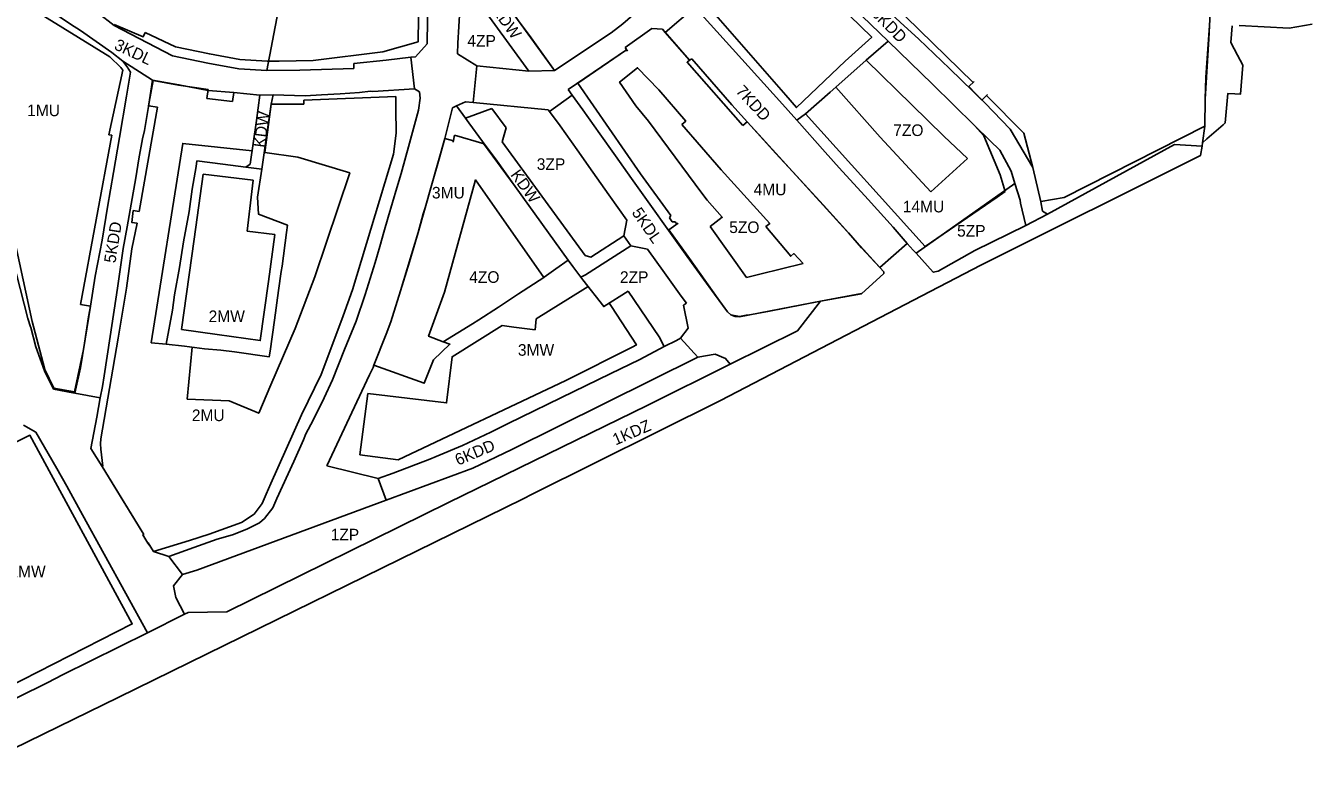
# Model space of a CAD drawing. Extents: x 7422310 to 7423642, y 5546060 to 5546927.
# Drawn here: x 7422901 to 7423455, y 5546113 to 5546434 of the extents above; entities that cross this region are included whole.
import ezdxf

# ---------------------------------------------------------------- set-up
doc = ezdxf.new("R2010")
doc.units = 0
for name, color, linetype in [('linie_rozgraniczajace', 7, 'Continuous'), ('linie_zabudowy_nieprzekraczalne', 7, 'Continuous'), ('linie_zabudowy_obowiązujace', 7, 'Continuous'), ('oznaczenia_przeznaczen', 7, 'Continuous')]:
    doc.layers.add(name, color=color, linetype=linetype)

msp = doc.modelspace()

# ---------------------------------------------------------------- linework, layer by layer
at = {"layer": 'linie_rozgraniczajace'}
for p, q in [((7423073.8, 5546425.75), (7423074.56, 5546477.74)), ((7423189.01, 5546441.58), (7423176.2, 5546430.66)), ((7423009.63, 5546439.75), (7423004.81, 5546414.23)), ((7423174.99, 5546432.06), (7423170.5, 5546432.37)), ((7423068.76, 5546420.18), (7423073.8, 5546425.75)), ((7423262.75, 5546418.7), (7423272.22, 5546426.88)), ((7422942.84, 5546418.27), (7422955.6, 5546410.13)), ((7423042.21, 5546417.2), (7423056.09, 5546418.71)), ((7423068.28, 5546406.4), (7423066.7, 5546419.94)), ((7423249.59, 5546407.03), (7423262.75, 5546418.7)), ((7423042.15, 5546415.05), (7423042.21, 5546417.2)), ((7423095.13, 5546416.2), (7423093.61, 5546400.5)), ((7423117.54, 5546413.93), (7423128.61, 5546414.21)), ((7423247.19, 5546404.93), (7423249.59, 5546407.03)), ((7423001.74, 5546403.6), (7423007.42, 5546403.74)), ((7423126.47, 5546396.57), (7423136.18, 5546403.62)), ((7423090.25, 5546393.7), (7423086.38, 5546399.01)), ((7423090.25, 5546393.7), (7423101.66, 5546397.94)), ((7423101.66, 5546397.94), (7423107.79, 5546389.55)), ((7423125.89, 5546397.37), (7423126.47, 5546396.57)), ((7423324.73, 5546388.94), (7423313.75, 5546400.32)), ((7423105.99, 5546383.55), (7423107.79, 5546389.55)), ((7423268.78, 5546385.58), (7423290.53, 5546362.07)), ((7423296.11, 5546386.01), (7423306.26, 5546376.43)), ((7422997.58, 5546373.98), (7422995.74, 5546372.63)), ((7423290.53, 5546362.07), (7423306.26, 5546376.43)), ((7423284.21, 5546335.6), (7423326.71, 5546365.57)), ((7423331.4, 5546347.59), (7423340.71, 5546352.47)), ((7423338.66, 5546353.63), (7423340.71, 5546352.47)), ((7423158.42, 5546343.08), (7423159.71, 5546349.88)), ((7423195.52, 5546347.13), (7423211.18, 5546325.11)), ((7423158.42, 5546343.08), (7423161.49, 5546338.78)), ((7423161.49, 5546338.78), (7423168.62, 5546337.4)), ((7423182.86, 5546298.95), (7423190.23, 5546290.85)), ((7422922.18, 5546275.32), (7422933.1, 5546273.27)), ((7422900.04, 5546261.52), (7422905.28, 5546258.55)), ((7422933.88, 5546243.7), (7422942.99, 5546228.95)), ((7423052.7, 5546238.61), (7423056.15, 5546229.3)), ((7422962.6, 5546205.08), (7422955.92, 5546207.18)), ((7422962.6, 5546205.08), (7422968.5, 5546197.26))]:
    msp.add_line(p, q, dxfattribs=at)
for points in [[(7423313.75, 5546400.32), (7423298.5, 5546415.11), (7423285.3, 5546427.74), (7423277.34, 5546435.03), (7423262.5, 5546448.96), (7423255.17, 5546455.86), (7423251.35, 5546459.53), (7423226, 5546483.92), (7423236.03, 5546494.6), (7423239.99, 5546499.12), (7423256.78, 5546518), (7423269.78, 5546532.29), (7423283.63, 5546547.12)], [(7423410.47, 5546433.48), (7423410.85, 5546441.62), (7423411.22, 5546452.41), (7423412.44, 5546471.67), (7423413.16, 5546487.99)], [(7423226, 5546483.92), (7423221.13, 5546476.36), (7423210.64, 5546464.93), (7423192.78, 5546445.64), (7423189.01, 5546441.58), (7423225.4, 5546401.19), (7423232.87, 5546392.89), (7423245.09, 5546379.05), (7423251.02, 5546372.38), (7423263.59, 5546358.66), (7423274.33, 5546346.76), (7423280.39, 5546339.82)], [(7423221.13, 5546476.36), (7423246.19, 5546452.06), (7423272.22, 5546426.88), (7423291.22, 5546408.42), (7423309.4, 5546390.63), (7423315.98, 5546384.15), (7423320.29, 5546380.02), (7423325.04, 5546370.95), (7423326.71, 5546365.57), (7423328.94, 5546358.36), (7423329.06, 5546357.09), (7423331.4, 5546347.59)], [(7423089.1, 5546469.47), (7423092.3, 5546464.88), (7423096.86, 5546458.12), (7423100.38, 5546453.19), (7423106.34, 5546444.85), (7423118.48, 5546428.31), (7423128.61, 5546414.21), (7423153, 5546430.51), (7423157.97, 5546434.29)], [(7422942.84, 5546418.27), (7422938.07, 5546422.01), (7422924.52, 5546431.41), (7422920.21, 5546434.18), (7422910.98, 5546440.54), (7422905.16, 5546444.71), (7422898.7, 5546448.79), (7422895.11, 5546450.46), (7422890.01, 5546452.75), (7422875.8, 5546457.17), (7422869.23, 5546459.14), (7422867.87, 5546459.46), (7422850.77, 5546464.93), (7422848.28, 5546453.48), (7422850.16, 5546448.92), (7422858.34, 5546432.53), (7422866.53, 5546416.28), (7422868.25, 5546412.95), (7422873.93, 5546400.01), (7422878.61, 5546392.2), (7422880.68, 5546389.97), (7422882.72, 5546383.91)], [(7422896.1, 5546464.02), (7422902.1, 5546461.88), (7422903.84, 5546461.21), (7422914.58, 5546452.89), (7422924.93, 5546444.52), (7422939, 5546433.61), (7422964.13, 5546420.6), (7422979.3, 5546417.43), (7422992.67, 5546414.98), (7423004.81, 5546414.23), (7423018.96, 5546414.36), (7423042.15, 5546415.05)], [(7423117.54, 5546413.93), (7423094.37, 5546445.85), (7423092.01, 5546447.67), (7423088.2, 5546447.7), (7423087.01, 5546425.95), (7423086.77, 5546421.45), (7423095.13, 5546416.2), (7423117.54, 5546413.93)], [(7423420.19, 5546433.55), (7423419.62, 5546426.25), (7423422.49, 5546420.89), (7423424.79, 5546416.61), (7423423.76, 5546404), (7423421.41, 5546404.17), (7423418.37, 5546404.38), (7423417.27, 5546391.68), (7423416.41, 5546390.93), (7423409.39, 5546384.8), (7423407.47, 5546383.13), (7423407.27, 5546381.7), (7423406.56, 5546377.62), (7423312.11, 5546330.42), (7423200.03, 5546272.25), (7423119.24, 5546231.93), (7423114.79, 5546229.75), (7422941.03, 5546144.48), (7422875.82, 5546112.55)], [(7423158.94, 5546424.1), (7423170.5, 5546432.37)], [(7423187.64, 5546419.3), (7423186.61, 5546418.64), (7423176.2, 5546430.66), (7423174.99, 5546432.06)], [(7423410.47, 5546433.48), (7423409.52, 5546419.62), (7423408.93, 5546411.19), (7423408.64, 5546401.87), (7423408.44, 5546390.23), (7423407.47, 5546383.13)], [(7423454.7, 5546434.19), (7423444.69, 5546432.48), (7423423.27, 5546433.58)], [(7423158.94, 5546424.1), (7423159.57, 5546423.17), (7423134.4, 5546406.07)], [(7422942.84, 5546418.27), (7422944.64, 5546415.83), (7422946.03, 5546413.53), (7422944.37, 5546403.26), (7422941.36, 5546385.4), (7422938.72, 5546370.37), (7422936.2, 5546355.47), (7422933.96, 5546341.18), (7422930.94, 5546325.71), (7422928.93, 5546312.84), (7422928.04, 5546308.14), (7422926.29, 5546296.91), (7422924.63, 5546286.28)], [(7423056.09, 5546418.71), (7423066.7, 5546419.94), (7423068.76, 5546420.18)], [(7423268.54, 5546329.5), (7423260.76, 5546337.96), (7423255.07, 5546344.32), (7423244.3, 5546356.22), (7423236.08, 5546365.29), (7423232.89, 5546368.81), (7423223.89, 5546378.5), (7423218.47, 5546384.35), (7423208.89, 5546395.05), (7423204.94, 5546399.47), (7423187.64, 5546419.3)], [(7423296.11, 5546386.01), (7423282.31, 5546399.53), (7423262.75, 5546418.7)], [(7423195.52, 5546347.13), (7423199.42, 5546350.06), (7423200.73, 5546351.04), (7423194.29, 5546358.45), (7423192.03, 5546361.38), (7423169.09, 5546392.38), (7423163.55, 5546399.02), (7423156.56, 5546409.23), (7423164.34, 5546415.42), (7423173.43, 5546405.92), (7423185.02, 5546392.5), (7423183.43, 5546390.95)], [(7422997.58, 5546373.98), (7423000.25, 5546392.66), (7423001.74, 5546403.6), (7422990.59, 5546404.8), (7422979.49, 5546405.69), (7422966.95, 5546408.1), (7422955.6, 5546410.13), (7422953.84, 5546398.71), (7422952.12, 5546388.38), (7422951.31, 5546384.86), (7422949.74, 5546376.23), (7422948.36, 5546368.1), (7422946.38, 5546356.7), (7422944.6, 5546346.93), (7422942.96, 5546337.61), (7422940.51, 5546320.54), (7422937.34, 5546299.69), (7422934.69, 5546282.86), (7422934.04, 5546278.27), (7422933.1, 5546273.27), (7422931.54, 5546264.99), (7422929.01, 5546251.47)], [(7423249.59, 5546407.03), (7423268.78, 5546385.58)], [(7423070.09, 5546397.23), (7423070.71, 5546402.27), (7423070.46, 5546405.03), (7423068.28, 5546406.4), (7423050.37, 5546405.21), (7423049.38, 5546405.29), (7423044.65, 5546404.83), (7423036.3, 5546404.24), (7423028.33, 5546403.75), (7423021.25, 5546403.36), (7423007.42, 5546403.74), (7423006.59, 5546399.81), (7423004.81, 5546386.78), (7423002.56, 5546371.78), (7423000.75, 5546359.7)], [(7423243.06, 5546314.91), (7423208.19, 5546308.26), (7423206.38, 5546308.39), (7423204.49, 5546309.09), (7423202.98, 5546310.29), (7423197.42, 5546317.97), (7423192.79, 5546324.22), (7423185.71, 5546334.11), (7423161.72, 5546367.72), (7423154.85, 5546377.47), (7423148.05, 5546387), (7423140.73, 5546397.36), (7423136.18, 5546403.62), (7423134.4, 5546406.07)], [(7423247.19, 5546404.93), (7423236.54, 5546395.6), (7423232.87, 5546392.89)], [(7422962.6, 5546205.08), (7422973.33, 5546208.83), (7422983.45, 5546212.48), (7422990.02, 5546214.37), (7422996.08, 5546216.82), (7423001.66, 5546219.51), (7423003.8, 5546221.4), (7423007.31, 5546225.96), (7423009.06, 5546229.93), (7423016.32, 5546245.9), (7423020.53, 5546255.26), (7423021.58, 5546257.84), (7423024.69, 5546263.69), (7423029.45, 5546273.3), (7423032.98, 5546281.12), (7423038.17, 5546294.1), (7423043.18, 5546306.38), (7423047.05, 5546317.8), (7423051.34, 5546331.52), (7423053.35, 5546338.41), (7423055.15, 5546344.58), (7423057.01, 5546351.04), (7423058.81, 5546357.44), (7423060.72, 5546363.72), (7423062.51, 5546369.9), (7423066.18, 5546382.92), (7423070.09, 5546397.23)], [(7423050.86, 5546287.45), (7423056.09, 5546300.76), (7423058.06, 5546306.11), (7423062.34, 5546319.38), (7423066.19, 5546331.82), (7423069.9, 5546344.45), (7423072.05, 5546352.59), (7423072.88, 5546355.17), (7423075.38, 5546363.7), (7423079.25, 5546377.16), (7423081.35, 5546385.04), (7423084.6, 5546398.19)], [(7423084.6, 5546398.19), (7423086.38, 5546399.01), (7423090.31, 5546400.82), (7423093.61, 5546400.5), (7423125.89, 5546397.37)], [(7423159.71, 5546349.88), (7423151.93, 5546360.78), (7423145.05, 5546370.53), (7423138.27, 5546380.06), (7423130.97, 5546390.37), (7423126.47, 5546396.57)], [(7423134.49, 5546332.65), (7423111.69, 5546364.32), (7423103.17, 5546376.16), (7423097.59, 5546383.64), (7423091.66, 5546391.78), (7423090.25, 5546393.7)], [(7423235.55, 5546331.21), (7423231.58, 5546335.44), (7423230.26, 5546334.3), (7423219.59, 5546347.06), (7423221.22, 5546348.34), (7423200.31, 5546371.45), (7423183.43, 5546390.95)], [(7423334.49, 5546372.47), (7423324.73, 5546388.94)], [(7422882.72, 5546383.91), (7422884.75, 5546377.58), (7422885.13, 5546377.71), (7422886.89, 5546372.24), (7422887.19, 5546372.34), (7422887.25, 5546372.18), (7422889.62, 5546365.57), (7422887.5, 5546364.99), (7422890.5, 5546351.82), (7422901.88, 5546307.51), (7422902.98, 5546303.83), (7422903.21, 5546303.56), (7422905.4, 5546295.31), (7422909.08, 5546284.94), (7422912.92, 5546277.1)], [(7423105.99, 5546383.55), (7423141.8, 5546334.6), (7423144.26, 5546333.88), (7423158.42, 5546343.08)], [(7423340.71, 5546352.47), (7423395.47, 5546382.37), (7423407.27, 5546381.7)], [(7423002.56, 5546371.78), (7422995.74, 5546372.63), (7422985.78, 5546373.88), (7422974.65, 5546375.35), (7422974.32, 5546372.99), (7422972.58, 5546363.11), (7422971.29, 5546353.6), (7422968.89, 5546340.54), (7422967.21, 5546329.4), (7422964.96, 5546317.72), (7422964.13, 5546311.05), (7422961.49, 5546296.42), (7422969.36, 5546295.55), (7422977.93, 5546294.39), (7422984.94, 5546293.88), (7422990.91, 5546293.07), (7423005.79, 5546291.03), (7423006.14, 5546293.47), (7423008.01, 5546306.75), (7423009.84, 5546319.5), (7423010.98, 5546327.68), (7423011.32, 5546330.05), (7423013.22, 5546344.49), (7423013.66, 5546347.66), (7423001.14, 5546352.45), (7423000.75, 5546359.7)], [(7423334.49, 5546372.47), (7423337.81, 5546357.64), (7423338.66, 5546353.63)], [(7423123.93, 5546325.08), (7423094.58, 5546367.13), (7423081.18, 5546318.77), (7423074.37, 5546299.85), (7423080.62, 5546297.48)], [(7423331.4, 5546347.59), (7423309.44, 5546336.79), (7423293.68, 5546327.82), (7423291.61, 5546327.42), (7423284.21, 5546335.6), (7423282.98, 5546336.96), (7423280.39, 5546339.82), (7423268.54, 5546329.5), (7423270.31, 5546327.56), (7423270.28, 5546326.84), (7423260.73, 5546318.13), (7423243.06, 5546314.91), (7423233.08, 5546302.2), (7423204.23, 5546287.81), (7423168.47, 5546269.98), (7423082.94, 5546228.32), (7422987.51, 5546181.19), (7422970.9, 5546180.89), (7422969.35, 5546180.12), (7422953.34, 5546172.11)], [(7423160.31, 5546319.24), (7423149.75, 5546312.61), (7423140.77, 5546324.18), (7423139.85, 5546325.31), (7423141.88, 5546326.3), (7423161.49, 5546338.78)], [(7423185.39, 5546314.05), (7423183.09, 5546317.15), (7423175.94, 5546327.13), (7423168.62, 5546337.4)], [(7423030.54, 5546244.05), (7423048.9, 5546283.16), (7423050.47, 5546286.38), (7423050.86, 5546287.45), (7423072.5, 5546279.63), (7423076.54, 5546289.75), (7423083.59, 5546296.43), (7423080.62, 5546297.48), (7423093.24, 5546305.14), (7423096.06, 5546306.86), (7423104.42, 5546312.31), (7423113.03, 5546318.16), (7423123.93, 5546325.08), (7423124.18, 5546325.24), (7423129.21, 5546328.88), (7423134.49, 5546332.65), (7423136.39, 5546329.82), (7423139.85, 5546325.31)], [(7423235.55, 5546331.21), (7423216.95, 5546326.56), (7423211.18, 5546325.11)], [(7423182.86, 5546298.95), (7423181.05, 5546298.05), (7423175.71, 5546295.39), (7423173.64, 5546299.55), (7423160.31, 5546319.24)], [(7423185.39, 5546314.05), (7423184.14, 5546313.16), (7423186.16, 5546303.34), (7423182.86, 5546298.95)], [(7422969.35, 5546180.12), (7422965.58, 5546187.33), (7422964.55, 5546192.33), (7422968.5, 5546197.26), (7422974.64, 5546199.1), (7423056.15, 5546229.3), (7423093.38, 5546243.1), (7423110.19, 5546251.06), (7423190.23, 5546290.85), (7423197.78, 5546292.13), (7423202.22, 5546290.27), (7423204.23, 5546287.81)], [(7423175.71, 5546295.39), (7423165.3, 5546289.89), (7423152.48, 5546283.66), (7423136.84, 5546276.11), (7423108.63, 5546262.31), (7423103.16, 5546259.56), (7423101.11, 5546258.57), (7423088.99, 5546252.87), (7423077.59, 5546248.14), (7423074.85, 5546246.93), (7423059.07, 5546240.95), (7423052.7, 5546238.61), (7423030.54, 5546244.05)], [(7422912.92, 5546277.1), (7422921.27, 5546275.49), (7422922.18, 5546275.32), (7422924.63, 5546286.28)], [(7422953.34, 5546172.11), (7422925.45, 5546222.98), (7422918.66, 5546235.36), (7422914.35, 5546242.9), (7422905.28, 5546258.55)], [(7422929.01, 5546251.47), (7422933.88, 5546243.7)], [(7422942.99, 5546228.95), (7422946.85, 5546222.68), (7422949.93, 5546217.5), (7422951.79, 5546214.54), (7422951.39, 5546214.3), (7422953.51, 5546210.72), (7422953.75, 5546210.86), (7422955.92, 5546207.18)], [(7422875.95, 5546134.22), (7422876.79, 5546134.17), (7422884.01, 5546137.67), (7422910.51, 5546150.81), (7422916.79, 5546154.09), (7422953.34, 5546172.11)]]:
    msp.add_lwpolyline(points, dxfattribs=at)
at = {"layer": 'linie_zabudowy_nieprzekraczalne'}
for p, q in [((7422936.77, 5546386.62), (7422942.78, 5546414.42)), ((7422924.54, 5546313.55), (7422938.07, 5546386.37)), ((7422938.07, 5546386.37), (7422936.77, 5546386.62)), ((7422998.81, 5546367.01), (7422977.41, 5546369.59)), ((7422996.27, 5546345.14), (7422998.81, 5546367.01)), ((7422949.8, 5546353.53), (7422947.3, 5546353.94)), ((7423008.24, 5546343.7), (7422996.27, 5546345.14)), ((7422968.01, 5546302.71), (7422983.43, 5546300.55)), ((7422940.78, 5546298.95), (7422933.33, 5546255.67)), ((7422961.49, 5546296.42), (7422954.93, 5546297.04)), ((7422921.96, 5546275.95), (7422925.91, 5546294.14))]:
    msp.add_line(p, q, dxfattribs=at)
for points in [[(7423069.83, 5546426.53), (7423070.49, 5546468.22), (7423068.99, 5546473.81)], [(7423208.63, 5546456.53), (7423195.04, 5546441.5), (7423228.09, 5546403.61), (7423232.68, 5546398.29), (7423253.71, 5546418.3), (7423265.12, 5546428.67), (7423241.08, 5546452.13)], [(7422942.78, 5546414.42), (7422941.94, 5546415.53), (7422937.13, 5546420.13), (7422896.78, 5546445.27)], [(7422939.01, 5546434.04), (7422951.6, 5546428.79), (7422952.33, 5546430.62)], [(7422952.33, 5546430.62), (7422965.48, 5546424.4), (7422980.07, 5546421.36), (7422993.15, 5546418.96), (7423004.91, 5546418.23), (7423010.06, 5546418.31)], [(7423010.06, 5546418.31), (7423024.76, 5546418.5), (7423054.74, 5546422.31), (7423069.83, 5546426.53)], [(7422979.54, 5546406.01), (7422966.79, 5546407.95), (7422955.86, 5546409.96), (7422953.9, 5546399.08)], [(7422978.91, 5546402.13), (7422979.54, 5546406.01)], [(7422989.98, 5546400.89), (7422978.91, 5546402.13)], [(7423001.74, 5546403.6), (7422990.59, 5546404.8), (7422989.98, 5546400.89)], [(7423060.26, 5546403.03), (7423020.73, 5546401.43), (7423020.75, 5546399.74)], [(7422957.75, 5546398.5), (7422949.83, 5546353.52)], [(7422953.9, 5546399.08), (7422957.75, 5546398.5)], [(7423006.59, 5546399.81), (7423006.59, 5546399.81), (7423003.88, 5546379.02)], [(7423020.75, 5546399.74), (7423006.59, 5546399.81)], [(7422954.93, 5546297.04), (7422968.59, 5546382.84), (7422998.38, 5546379.62)], [(7423003.88, 5546379.02), (7423018.08, 5546376.99), (7423040.47, 5546370.15), (7423025.44, 5546325.47), (7423016.97, 5546303.16), (7423006.55, 5546278.97), (7423001.27, 5546266.71), (7422988.49, 5546272.01), (7422970.48, 5546272.76)], [(7422977.41, 5546369.59), (7422973.48, 5546341.59), (7422968.01, 5546302.71)], [(7422890.48, 5546361.27), (7422894.4, 5546349.33), (7422903.76, 5546306.15), (7422903.76, 5546306.15), (7422904.38, 5546303.97), (7422909.15, 5546285.59), (7422913.13, 5546277.45)], [(7422947.3, 5546353.94), (7422947.3, 5546353.94), (7422947.3, 5546353.94), (7422946.64, 5546348.82), (7422948.92, 5546348.5)], [(7422948.92, 5546348.5), (7422946.7, 5546337.41), (7422944.37, 5546320.57), (7422940.78, 5546298.95)], [(7422983.43, 5546300.55), (7423001.95, 5546298), (7423005.46, 5546323.48), (7423008.24, 5546343.7)], [(7423143.06, 5546321.24), (7423140.72, 5546319.76), (7423120.74, 5546307.29), (7423120.2, 5546302.66), (7423111.03, 5546303.81), (7423106.09, 5546304.54), (7423084.46, 5546291), (7423082.13, 5546271.17), (7423048.16, 5546275.14)], [(7422925.91, 5546294.14), (7422928.93, 5546312.84), (7422924.54, 5546313.55)], [(7423061.26, 5546246.58), (7423133.45, 5546280.79), (7423161.94, 5546295.13), (7423163.82, 5546296.08), (7423153.17, 5546312.64), (7423152.29, 5546314)], [(7422970.48, 5546272.76), (7422972.67, 5546295.11)], [(7422913.13, 5546277.45), (7422921.96, 5546275.95)], [(7423048.16, 5546275.14), (7423044.85, 5546248.8), (7423061.26, 5546246.58)], [(7422885.92, 5546145), (7422946.82, 5546175.98), (7422902.8, 5546257.21), (7422868.43, 5546240.14), (7422828.79, 5546221.69), (7422819.61, 5546240.79)], [(7422933.33, 5546255.67), (7422933.14, 5546253.57), (7422933.26, 5546251.28), (7422934.18, 5546243.89)]]:
    msp.add_lwpolyline(points, dxfattribs=at)
at = {"layer": 'linie_zabudowy_obowiązujace'}
for p, q in [((7423279.78, 5546437.34), (7423308.74, 5546409.07)), ((7423174.99, 5546432.06), (7423170.5, 5546432.37)), ((7423410.15, 5546427.9), (7423410.47, 5546433.48)), ((7423158.94, 5546424.1), (7423159.93, 5546422.63)), ((7423306.8, 5546407.15), (7423306.8, 5546407.15)), ((7423309.19, 5546409.54), (7423306.96, 5546407.33)), ((7423306.96, 5546407.33), (7423312.51, 5546401.53)), ((7423312.51, 5546401.53), (7423314.98, 5546403.94)), ((7423314.51, 5546403.49), (7423330.58, 5546387.27)), ((7423211.5, 5546392.11), (7423209.66, 5546390.56)), ((7423216.48, 5546386.66), (7423211.5, 5546392.11)), ((7423347.85, 5546359.51), (7423408.44, 5546390.23)), ((7423085.11, 5546383.97), (7423081.35, 5546385.04)), ((7423085.59, 5546386.41), (7423084.93, 5546383.35)), ((7423337.92, 5546357.85), (7423347.85, 5546359.51)), ((7423178.58, 5546351.87), (7423178.01, 5546350.81)), ((7423181.72, 5546348.46), (7423177.72, 5546345.61)), ((7423178.01, 5546350.81), (7423179.26, 5546349.04)), ((7423179.26, 5546349.04), (7423180.52, 5546349.06)), ((7423180.52, 5546349.06), (7423181.18, 5546348.09)), ((7423270.28, 5546326.84), (7423270.31, 5546327.56)), ((7423202.98, 5546310.29), (7423204.49, 5546309.09)), ((7423204.49, 5546309.09), (7423208.2, 5546308.39)), ((7422993.91, 5546219.68), (7422999.25, 5546223.28))]:
    msp.add_line(p, q, dxfattribs=at)
for points in [[(7423096.86, 5546458.12), (7423128.61, 5546414.21)], [(7423128.61, 5546414.21), (7423153, 5546430.51), (7423157.97, 5546434.29), (7423165.45, 5546440.76)], [(7423170.5, 5546432.37), (7423158.94, 5546424.1)], [(7423209.66, 5546390.56), (7423185.6, 5546417.77), (7423186.61, 5546418.64), (7423174.99, 5546432.06)], [(7423322.53, 5546362.2), (7423320.41, 5546369.33), (7423313.3, 5546386.08), (7423309.4, 5546390.63), (7423291.22, 5546408.42), (7423272.22, 5546426.88)], [(7423408.44, 5546390.23), (7423408.64, 5546401.87), (7423410.15, 5546427.9)], [(7423159.57, 5546423.17), (7423138.64, 5546408.87)], [(7423138.64, 5546408.87), (7423165.58, 5546369.7), (7423178.58, 5546351.87)], [(7423060.3, 5546397.72), (7423060.26, 5546403.03)], [(7423031.9, 5546293.22), (7423037.62, 5546308.57), (7423041.64, 5546319.81), (7423059.27, 5546378.2), (7423060.38, 5546387.23), (7423060.3, 5546397.72)], [(7423236.54, 5546395.6), (7423288.03, 5546338.43)], [(7423081.35, 5546385.04), (7423069.9, 5546344.45), (7423062.34, 5546319.38), (7423058.06, 5546306.11), (7423056.09, 5546300.76), (7423050.86, 5546287.45)], [(7423098.31, 5546382.68), (7423085.59, 5546386.41)], [(7423270.31, 5546327.56), (7423268.54, 5546329.5), (7423258.65, 5546340.36), (7423216.48, 5546386.66)], [(7423330.58, 5546387.27), (7423330.58, 5546387.27), (7423330.58, 5546387.27), (7423330.58, 5546387.27), (7423334.49, 5546372.47), (7423337.94, 5546357.76)], [(7423134.49, 5546332.65), (7423111.69, 5546364.32), (7423098.08, 5546382.86), (7423098.04, 5546382.87)], [(7423288.03, 5546338.43), (7423319.04, 5546359.78)], [(7423319.03, 5546359.78), (7423322.57, 5546362.21)], [(7423177.72, 5546345.61), (7423185.91, 5546334.26), (7423199.54, 5546315.11)], [(7423260.73, 5546318.13), (7423270.28, 5546326.84)], [(7423208.2, 5546308.39), (7423210.99, 5546308.89), (7423212.49, 5546309.06), (7423220.36, 5546310.52), (7423243.06, 5546314.91), (7423260.74, 5546318.21)], [(7423199.54, 5546315.11), (7423202.98, 5546310.29)], [(7423006.45, 5546236.41), (7423019.69, 5546265.95), (7423028.2, 5546283.39), (7423031.9, 5546293.22)], [(7422933.88, 5546243.7), (7422951.79, 5546214.54), (7422951.39, 5546214.3), (7422953.51, 5546210.72), (7422954.57, 5546209.47), (7422955.92, 5546207.18), (7422955.92, 5546207.18)], [(7422999.25, 5546223.28), (7423002.76, 5546227.84), (7423004.51, 5546231.81), (7423006.45, 5546236.41)], [(7422955.92, 5546207.18), (7422971.52, 5546211.89), (7422979.9, 5546214.68), (7422993.91, 5546219.68)]]:
    msp.add_lwpolyline(points, dxfattribs=at)

# ---------------------------------------------------------------- texts
at = {"layer": 'oznaczenia_przeznaczen'}
for s, rotation, p in [('KDW', 305.7049, (7423101.48, 5546439.98)), ('8KDD', 314.5873, (7423264.58, 5546438.47)), ('3KDL', 334.7315, (7422938.7, 5546423.59)), ('7KDD', 312.6745, (7423206.27, 5546405.09)), ('KDW', 82.6474, (7423003.97, 5546380.85)), ('KDW', 305.7049, (7423109.42, 5546369.33)), ('5KDL', 304.5331, (7423161.6, 5546353.08)), ('5KDD', 80.8346, (7422939.56, 5546331.11)), ('1KDZ', 23.2502, (7423154.88, 5546252.79)), ('6KDD', 22.9424, (7423087.06, 5546244.07))]:
    msp.add_text(s, height=5, rotation=rotation, dxfattribs=at).set_placement(p)
for s, p in [('4ZP', (7423091.07, 5546424.56)), ('1MU', (7422901.63, 5546394.6)), ('7ZO', (7423274.36, 5546386.04)), ('3ZP', (7423120.94, 5546371.45)), ('3MU', (7423075.83, 5546359.15)), ('4MU', (7423214.26, 5546360.53)), ('14MU', (7423278.48, 5546353.16)), ('5ZO', (7423203.77, 5546344.28)), ('5ZP', (7423301.83, 5546342.74)), ('4ZO', (7423091.87, 5546322.83)), ('2ZP', (7423156.74, 5546322.8)), ('2MW', (7422979.71, 5546305.93)), ('3MW', (7423112.82, 5546291.44)), ('2MU', (7422972.49, 5546263.31)), ('1ZP', (7423032.24, 5546211.94)), ('1MW', (7422893.98, 5546196.07))]:
    msp.add_text(s, height=5, dxfattribs=at).set_placement(p)

doc.saveas('drawing.dxf')
